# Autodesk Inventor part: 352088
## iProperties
Created: 2006-07
Part Number: 352088
Material: St
Description: Rillenkugellager
Vendor: Autodesk Inc.
Document SubType Name: Modeling
Standard: DIN 625 T1
Designer: I.Baliuc
Standards Organization: DIN
Language: de-DE
Size Designation: 6006 - 30 x 55 x 13
Categories: <MemberInstance Version="R10.0.0"><Categories><Category DisplayName="Wellenteile" InternalName="7f7aeb1f-a693-4053-b835-cee3144e0d98" Mnemonic="SHFT"><Category
Density: 7.86 g/cm^3
Mass: 111.768 g
Surface Area: 107.517 cm^2
Volume: 14.2199 cm^3
Abmessung: 6006-30x55x13
Author: T.Messerschmitt
Comments: DIN 625 T1 - 6006 - 30 x 55 x 13
Revision Number: 352088
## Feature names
1. Körper [Revolution]
2. Rundung1 [Fillet]
3. Kugel [Revolution]
4. Kugeln [Circular Pattern]
